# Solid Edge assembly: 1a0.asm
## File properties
Author: edge
Template: jis assembly.asm
Last saved by: edge
Revision: 20
Application: Solid Edge
文書内容のタイプ: 1
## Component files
1a1.par
1a2.par
1a3.par
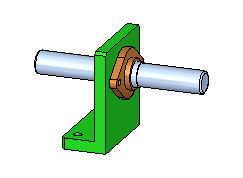
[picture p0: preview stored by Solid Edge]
